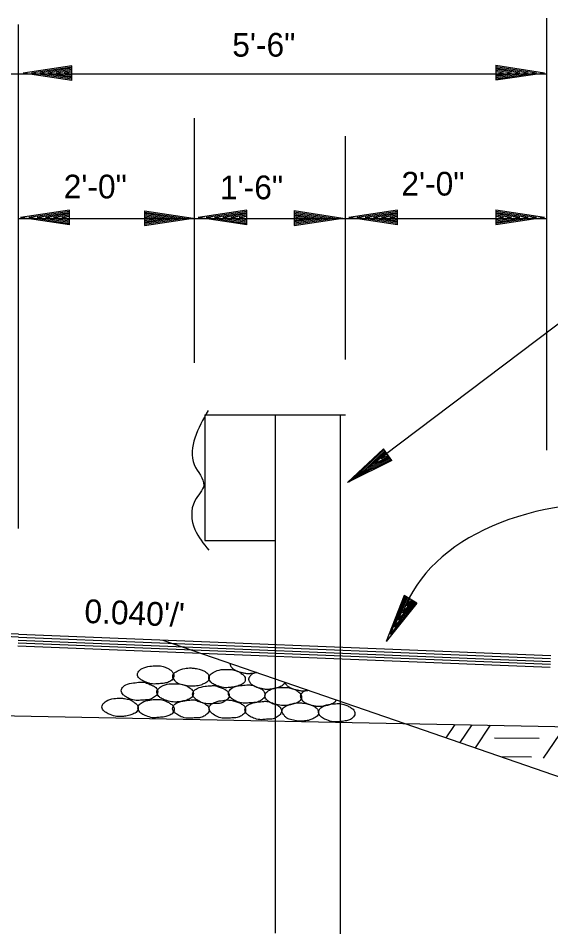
# Model space of a CAD drawing. Extents: x 1926836 to 1933254, y 596317 to 604524.
# Drawn here: x 1928623.7 to 1928757.8, y 602552.3 to 602783 of the extents above; entities that cross this region are included whole.
import ezdxf

# ---------------------------------------------------------------- set-up
doc = ezdxf.new("R2010")
doc.units = 0
doc.layers.add('Default', color=7, linetype='Continuous')
doc.layers.add('R_Annotation', color=7, linetype='Continuous')

msp = doc.modelspace()

# ---------------------------------------------------------------- linework, layer by layer
at = {"layer": 'Default'}
for p, q in [((1928623.71, 602654.37), (1928623.71, 602781.38)), ((1928756.85, 602674.17), (1928756.85, 602782.96)), ((1928637.18, 602771), (1928624.91, 602769.16)), ((1928637.18, 602770.68), (1928626.97, 602769.16)), ((1928637.18, 602770.36), (1928629.07, 602769.16)), ((1928637.18, 602770.06), (1928631.13, 602769.16)), ((1928637.18, 602769.75), (1928633.19, 602769.16)), ((1928637.18, 602769.43), (1928635.25, 602769.16)), ((1928637.18, 602767.3), (1928637.18, 602771)), ((1928743.96, 602771.12), (1928756.24, 602769.26)), ((1928743.96, 602771.12), (1928743.96, 602767.42)), ((1928743.96, 602770.8), (1928754.18, 602769.26)), ((1928743.96, 602770.48), (1928752.07, 602769.26)), ((1928743.96, 602770.19), (1928750.01, 602769.26)), ((1928743.96, 602769.87), (1928747.95, 602769.26)), ((1928743.96, 602769.55), (1928745.9, 602769.26)), ((1928743.96, 602767.42), (1928756.24, 602769.26)), ((1928743.96, 602768.67), (1928747.95, 602769.26)), ((1928743.96, 602768.05), (1928752.07, 602769.26)), ((1928743.96, 602767.74), (1928754.18, 602769.26)), ((1928743.96, 602768.35), (1928750.01, 602769.26)), ((1928743.96, 602768.99), (1928745.9, 602769.26)), ((1928427.69, 602768.94), (1928756.85, 602768.94)), ((1928637.18, 602767.3), (1928624.91, 602769.16)), ((1928637.18, 602767.61), (1928626.97, 602769.16)), ((1928637.18, 602767.93), (1928629.07, 602769.16)), ((1928637.18, 602768.23), (1928631.13, 602769.16)), ((1928637.18, 602768.54), (1928633.19, 602769.16)), ((1928637.18, 602768.86), (1928635.25, 602769.16)), ((1928668.08, 602696.18), (1928668.08, 602757.79)), ((1928706.13, 602696.98), (1928706.13, 602753.3)), ((1928743.96, 602734.68), (1928756.24, 602732.82)), ((1928743.96, 602734.68), (1928743.96, 602730.98)), ((1928623.71, 602732.53), (1928756.85, 602732.53)), ((1928636.52, 602734.59), (1928624.25, 602732.75)), ((1928636.52, 602730.89), (1928624.25, 602732.75)), ((1928636.52, 602734.27), (1928626.3, 602732.75)), ((1928636.52, 602731.2), (1928626.3, 602732.75)), ((1928636.52, 602733.95), (1928628.41, 602732.75)), ((1928636.52, 602731.52), (1928628.41, 602732.75)), ((1928636.52, 602733.65), (1928630.47, 602732.75)), ((1928636.52, 602731.82), (1928630.47, 602732.75)), ((1928636.52, 602733.34), (1928632.53, 602732.75)), ((1928636.52, 602732.14), (1928632.53, 602732.75)), ((1928636.52, 602733.02), (1928634.59, 602732.75)), ((1928636.52, 602732.45), (1928634.59, 602732.75)), ((1928636.52, 602730.89), (1928636.52, 602734.59)), ((1928655.46, 602734.46), (1928667.74, 602732.6)), ((1928655.46, 602734.46), (1928655.46, 602730.76)), ((1928655.46, 602734.14), (1928665.68, 602732.6)), ((1928655.46, 602733.83), (1928663.57, 602732.6)), ((1928655.46, 602733.53), (1928661.51, 602732.6)), ((1928655.46, 602733.21), (1928659.45, 602732.6)), ((1928655.46, 602732.89), (1928657.4, 602732.6)), ((1928655.46, 602730.76), (1928667.74, 602732.6)), ((1928655.46, 602732.01), (1928659.45, 602732.6)), ((1928655.46, 602731.4), (1928663.57, 602732.6)), ((1928655.46, 602731.08), (1928665.68, 602732.6)), ((1928655.46, 602731.69), (1928661.51, 602732.6)), ((1928655.46, 602732.33), (1928657.4, 602732.6)), ((1928681.24, 602734.59), (1928668.96, 602732.75)), ((1928681.24, 602730.89), (1928668.96, 602732.75)), ((1928681.24, 602734.27), (1928671.02, 602732.75)), ((1928681.24, 602731.2), (1928671.02, 602732.75)), ((1928681.24, 602733.95), (1928673.13, 602732.75)), ((1928681.24, 602731.52), (1928673.13, 602732.75)), ((1928681.24, 602733.65), (1928675.19, 602732.75)), ((1928681.24, 602731.82), (1928675.19, 602732.75)), ((1928681.24, 602733.34), (1928677.24, 602732.75)), ((1928681.24, 602732.14), (1928677.24, 602732.75)), ((1928681.24, 602733.02), (1928679.3, 602732.75)), ((1928681.24, 602732.45), (1928679.3, 602732.75)), ((1928681.24, 602730.89), (1928681.24, 602734.59)), ((1928693.17, 602734.49), (1928705.44, 602732.63)), ((1928693.17, 602734.49), (1928693.17, 602730.79)), ((1928693.17, 602734.17), (1928703.39, 602732.63)), ((1928693.17, 602733.85), (1928701.28, 602732.63)), ((1928693.17, 602733.56), (1928699.22, 602732.63)), ((1928693.17, 602733.24), (1928697.16, 602732.63)), ((1928693.17, 602732.92), (1928695.1, 602732.63)), ((1928693.17, 602730.79), (1928705.44, 602732.63)), ((1928693.17, 602732.04), (1928697.16, 602732.63)), ((1928693.17, 602731.42), (1928701.28, 602732.63)), ((1928693.17, 602731.11), (1928703.39, 602732.63)), ((1928693.17, 602731.72), (1928699.22, 602732.63)), ((1928693.17, 602732.36), (1928695.1, 602732.63)), ((1928719.17, 602734.61), (1928706.89, 602732.77)), ((1928719.17, 602730.91), (1928706.89, 602732.77)), ((1928719.17, 602734.29), (1928708.95, 602732.77)), ((1928719.17, 602731.23), (1928708.95, 602732.77)), ((1928719.17, 602733.97), (1928711.06, 602732.77)), ((1928719.17, 602731.55), (1928711.06, 602732.77)), ((1928719.17, 602733.68), (1928713.11, 602732.77)), ((1928719.17, 602731.84), (1928713.11, 602732.77)), ((1928719.17, 602733.36), (1928715.17, 602732.77)), ((1928719.17, 602732.16), (1928715.17, 602732.77)), ((1928719.17, 602733.04), (1928717.23, 602732.77)), ((1928719.17, 602732.48), (1928717.23, 602732.77)), ((1928719.17, 602730.91), (1928719.17, 602734.61)), ((1928743.96, 602734.37), (1928754.18, 602732.82)), ((1928743.96, 602734.05), (1928752.07, 602732.82)), ((1928743.96, 602733.75), (1928750.01, 602732.82)), ((1928743.96, 602733.43), (1928747.95, 602732.82)), ((1928743.96, 602733.12), (1928745.9, 602732.82)), ((1928743.96, 602730.98), (1928756.24, 602732.82)), ((1928743.96, 602732.23), (1928747.95, 602732.82)), ((1928743.96, 602731.62), (1928752.07, 602732.82)), ((1928743.96, 602731.3), (1928754.18, 602732.82)), ((1928743.96, 602731.91), (1928750.01, 602732.82)), ((1928743.96, 602732.55), (1928745.9, 602732.82)), ((1928706.94, 602666.13), (1928775.96, 602718.29)), ((1928670.63, 602683.06), (1928670.63, 602651.35)), ((1928670.63, 602683.06), (1928706.13, 602683.06)), ((1928688.39, 602683.06), (1928688.39, 602552.42)), ((1928704.71, 602682.91), (1928704.71, 602552.29)), ((1928715.65, 602674.51), (1928706.62, 602665.99)), ((1928715.84, 602674.27), (1928708.29, 602667.14)), ((1928716.04, 602673.98), (1928710.08, 602668.41)), ((1928716.16, 602673.72), (1928711.74, 602669.56)), ((1928716.35, 602673.51), (1928713.41, 602670.73)), ((1928716.99, 602672.55), (1928713.41, 602670.73)), ((1928716.52, 602673.24), (1928715.11, 602671.92)), ((1928716.87, 602672.83), (1928715.11, 602671.92)), ((1928717.73, 602671.52), (1928715.65, 602674.51)), ((1928717.73, 602671.52), (1928706.62, 602665.99)), ((1928717.58, 602671.75), (1928708.29, 602667.14)), ((1928717.36, 602672.02), (1928710.08, 602668.41)), ((1928717.19, 602672.28), (1928711.74, 602669.56)), ((1928670.63, 602651.35), (1928688.39, 602651.35)), ((1928720.86, 602637.49), (1928716.3, 602625.92)), ((1928724.04, 602635.62), (1928716.3, 602625.92)), ((1928721.1, 602637.29), (1928717.33, 602627.71)), ((1928723.8, 602635.79), (1928717.33, 602627.71)), ((1928721.4, 602637.14), (1928718.38, 602629.55)), ((1928723.48, 602635.92), (1928718.38, 602629.55)), ((1928721.64, 602637), (1928719.39, 602631.29)), ((1928723.23, 602636.09), (1928719.39, 602631.29)), ((1928721.93, 602636.85), (1928720.44, 602633.1)), ((1928722.96, 602636.24), (1928720.44, 602633.1)), ((1928724.04, 602635.62), (1928720.86, 602637.49)), ((1928722.23, 602636.68), (1928721.49, 602634.86)), ((1928722.69, 602636.41), (1928721.49, 602634.86)), ((1928623.71, 602627.76), (1928476.7, 602633.64)), ((1928623.71, 602627.02), (1928476.7, 602632.9)), ((1928623.64, 602626.29), (1928757.74, 602620.92)), ((1928623.67, 602627.02), (1928757.76, 602621.66)), ((1928623.71, 602627.76), (1928757.8, 602622.39)), ((1928660.08, 602626.3), (1928721.07, 602605.25)), ((1928623.58, 602624.82), (1928757.68, 602619.45)), ((1928623.61, 602625.55), (1928757.71, 602620.19)), ((1928423.27, 602611.17), (1928815.02, 602603.38)), ((1928721.07, 602605.25), (1928844.61, 602562.6))]:
    msp.add_line(p, q, dxfattribs=at)
msp.add_ellipse((1928779.93, 602620.52), major_axis=(-60.55, 7.39), ratio=0.655798, start_param=4.712389, end_param=6.093533, dxfattribs=at)
for points in [[(1928671.49, 602684.09), (1928668.15, 602677.2), (1928667.98, 602670.49), (1928670.38, 602665.32), (1928668.15, 602661.4), (1928668.15, 602654.17), (1928671.68, 602648.95)], [(1928658.43, 602619.78), (1928656.81, 602619.68), (1928654.85, 602619.09), (1928653.82, 602618.16), (1928653.67, 602617.62), (1928654.16, 602616.64), (1928654.75, 602616.2), (1928655.88, 602615.66), (1928657.45, 602615.22), (1928658.28, 602615.22), (1928659.45, 602615.32), (1928660.78, 602615.47), (1928661.81, 602615.86), (1928662.69, 602616.69), (1928662.84, 602617.33), (1928662.54, 602618.21), (1928661.91, 602618.8), (1928661.22, 602619.19), (1928660.14, 602619.63), (1928659.45, 602619.78), (1928658.43, 602619.78)], [(1928676.96, 602620.48), (1928676.96, 602620.44), (1928676.96, 602620.38), (1928676.97, 602620.31), (1928677.04, 602620.04), (1928677.16, 602619.78), (1928677.31, 602619.52), (1928677.4, 602619.4), (1928677.51, 602619.28), (1928677.76, 602619.03), (1928678.04, 602618.84), (1928678.31, 602618.7), (1928678.57, 602618.57), (1928678.84, 602618.45), (1928679.12, 602618.35), (1928679.9, 602618.13), (1928680.69, 602617.96), (1928681.11, 602617.89), (1928681.31, 602617.87), (1928681.52, 602617.86), (1928682.11, 602617.89), (1928682.41, 602617.92), (1928682.7, 602617.96), (1928683.22, 602618.04), (1928683.73, 602618.14)], [(1928667.21, 602619.26), (1928665.59, 602619.16), (1928663.68, 602618.47), (1928662.7, 602617.69), (1928662.55, 602617.15), (1928663.09, 602616.12), (1928663.53, 602615.58), (1928664.71, 602615.09), (1928666.18, 602614.75), (1928667.01, 602614.65), (1928668.23, 602614.7), (1928669.61, 602614.94), (1928670.59, 602615.38), (1928671.62, 602616.17), (1928671.76, 602616.81), (1928671.47, 602617.69), (1928670.73, 602618.33), (1928670, 602618.67), (1928668.92, 602619.01), (1928668.23, 602619.16), (1928667.21, 602619.26)], [(1928676.34, 602618.89), (1928674.73, 602618.84), (1928672.77, 602618.15), (1928671.79, 602617.27), (1928671.64, 602616.68), (1928672.18, 602615.7), (1928672.72, 602615.26), (1928673.8, 602614.77), (1928675.36, 602614.33), (1928676.2, 602614.28), (1928677.37, 602614.38), (1928678.7, 602614.63), (1928679.73, 602615.02), (1928680.71, 602615.8), (1928680.85, 602616.39), (1928680.56, 602617.27), (1928679.82, 602617.86), (1928679.14, 602618.35), (1928678.06, 602618.69), (1928677.37, 602618.84), (1928676.34, 602618.89)], [(1928683.59, 602618.19), (1928683.29, 602618.07), (1928683.05, 602617.96), (1928682.82, 602617.83), (1928682.52, 602617.65), (1928682.27, 602617.44), (1928682.05, 602617.19), (1928681.94, 602617.05), (1928681.84, 602616.9), (1928681.76, 602616.77), (1928681.71, 602616.63), (1928681.68, 602616.5), (1928681.68, 602616.43), (1928681.69, 602616.36), (1928681.76, 602616.1), (1928681.88, 602615.83), (1928682.03, 602615.58), (1928682.13, 602615.46), (1928682.23, 602615.34), (1928682.48, 602615.09), (1928682.77, 602614.89), (1928683.03, 602614.75), (1928683.29, 602614.62), (1928683.57, 602614.5), (1928683.84, 602614.4), (1928684.62, 602614.18), (1928685.41, 602614.01), (1928686.25, 602613.91), (1928686.39, 602613.92), (1928686.54, 602613.92), (1928686.83, 602613.94), (1928687.42, 602614.01), (1928687.76, 602614.06), (1928688.09, 602614.12), (1928688.42, 602614.18), (1928688.74, 602614.26), (1928689.01, 602614.33), (1928689.27, 602614.42), (1928689.52, 602614.53), (1928689.77, 602614.65), (1928690.05, 602614.79), (1928690.31, 602614.96), (1928690.54, 602615.17), (1928690.65, 602615.29), (1928690.75, 602615.43), (1928690.82, 602615.55), (1928690.87, 602615.67)], [(1928654.37, 602615.69), (1928652.65, 602615.49), (1928650.74, 602615), (1928649.76, 602614.07), (1928649.61, 602613.53), (1928650.1, 602612.5), (1928650.69, 602612.06), (1928651.77, 602611.47), (1928653.34, 602611.08), (1928654.12, 602611.08), (1928655.35, 602611.18), (1928656.72, 602611.28), (1928657.75, 602611.77), (1928658.63, 602612.6), (1928658.78, 602613.24), (1928658.48, 602614.12), (1928657.75, 602614.71), (1928657.06, 602615), (1928655.98, 602615.44), (1928655.35, 602615.64), (1928654.37, 602615.69)], [(1928663.26, 602615.27), (1928661.64, 602615.22), (1928659.68, 602614.58), (1928658.7, 602613.65), (1928658.56, 602613.11), (1928659.1, 602612.09), (1928659.63, 602611.64), (1928660.71, 602611.15), (1928662.28, 602610.76), (1928663.11, 602610.66), (1928664.29, 602610.76), (1928665.61, 602611.01), (1928666.64, 602611.4), (1928667.62, 602612.18), (1928667.77, 602612.82), (1928667.48, 602613.7), (1928666.74, 602614.29), (1928666.05, 602614.73), (1928664.98, 602615.07), (1928664.29, 602615.22), (1928663.26, 602615.27)], [(1928672.32, 602614.77), (1928670.7, 602614.63), (1928668.74, 602614.09), (1928667.71, 602613.16), (1928667.57, 602612.62), (1928668.1, 602611.64), (1928668.64, 602611.2), (1928669.77, 602610.56), (1928671.29, 602610.22), (1928672.12, 602610.22), (1928673.3, 602610.31), (1928674.72, 602610.36), (1928675.7, 602610.85), (1928676.63, 602611.69), (1928676.78, 602612.32), (1928676.48, 602613.2), (1928675.8, 602613.79), (1928675.06, 602614.14), (1928674.03, 602614.48), (1928673.35, 602614.77), (1928672.32, 602614.77)], [(1928681.24, 602615), (1928679.62, 602614.81), (1928677.71, 602614.32), (1928676.73, 602613.38), (1928676.58, 602612.84), (1928677.12, 602611.82), (1928677.66, 602611.37), (1928678.74, 602610.79), (1928680.31, 602610.39), (1928681.09, 602610.39), (1928682.32, 602610.49), (1928683.64, 602610.59), (1928684.72, 602611.08), (1928685.65, 602611.91), (1928685.79, 602612.55), (1928685.5, 602613.43), (1928684.77, 602614.02), (1928684.03, 602614.32), (1928683, 602614.81), (1928682.27, 602614.95), (1928681.24, 602615)], [(1928690.82, 602615.69), (1928690.9, 602615.49), (1928691.01, 602615.29), (1928691.14, 602615.1), (1928691.29, 602614.91), (1928691.55, 602614.66), (1928691.83, 602614.47), (1928692.09, 602614.33), (1928692.36, 602614.2), (1928692.63, 602614.08), (1928692.91, 602613.98), (1928693.69, 602613.76), (1928694.48, 602613.59), (1928694.89, 602613.52), (1928695.1, 602613.5), (1928695.31, 602613.49), (1928695.9, 602613.52), (1928696.49, 602613.59), (1928696.79, 602613.63)], [(1928690.5, 602614.36), (1928688.88, 602614.32), (1928686.92, 602613.68), (1928685.94, 602612.75), (1928685.79, 602612.21), (1928686.33, 602611.18), (1928686.87, 602610.74), (1928687.95, 602610.25), (1928689.52, 602609.86), (1928690.35, 602609.76), (1928691.53, 602609.86), (1928692.85, 602610.1), (1928693.88, 602610.49), (1928694.86, 602611.28), (1928695.01, 602611.91), (1928694.71, 602612.8), (1928693.98, 602613.38), (1928693.29, 602613.83), (1928692.21, 602614.17), (1928691.53, 602614.32), (1928690.5, 602614.36)], [(1928696.37, 602613.77), (1928696.11, 602613.66), (1928695.98, 602613.59), (1928695.85, 602613.52), (1928695.56, 602613.34), (1928695.3, 602613.13), (1928695.08, 602612.88), (1928694.97, 602612.74), (1928694.87, 602612.59), (1928694.79, 602612.46), (1928694.74, 602612.32), (1928694.71, 602612.18), (1928694.71, 602612.12), (1928694.72, 602612.05), (1928694.79, 602611.78), (1928694.91, 602611.52), (1928695.07, 602611.27), (1928695.16, 602611.14), (1928695.26, 602611.02), (1928695.51, 602610.77), (1928695.8, 602610.58), (1928696.06, 602610.44), (1928696.33, 602610.31), (1928696.6, 602610.19), (1928696.88, 602610.09), (1928697.65, 602609.87), (1928698.44, 602609.7), (1928699.28, 602609.6), (1928699.42, 602609.6), (1928699.57, 602609.61), (1928699.87, 602609.63), (1928700.45, 602609.7), (1928700.79, 602609.75), (1928701.12, 602609.81), (1928701.45, 602609.87), (1928701.78, 602609.94), (1928702.04, 602610.02), (1928702.3, 602610.11), (1928702.55, 602610.22), (1928702.81, 602610.34), (1928703.08, 602610.48), (1928703.34, 602610.65), (1928703.57, 602610.86), (1928703.68, 602610.98), (1928703.73, 602611.05), (1928703.79, 602611.12), (1928703.83, 602611.2)], [(1928649.37, 602611.61), (1928647.75, 602611.56), (1928645.79, 602610.88), (1928644.86, 602609.99), (1928644.71, 602609.41), (1928645.2, 602608.43), (1928645.79, 602607.99), (1928646.82, 602607.5), (1928648.44, 602607.05), (1928649.22, 602607.01), (1928650.45, 602607.1), (1928651.77, 602607.35), (1928652.8, 602607.74), (1928653.73, 602608.52), (1928653.88, 602609.11), (1928653.58, 602609.99), (1928652.85, 602610.58), (1928652.16, 602611.07), (1928651.08, 602611.42), (1928650.4, 602611.56), (1928649.37, 602611.61)], [(1928658.43, 602611.33), (1928656.82, 602611.18), (1928654.86, 602610.59), (1928653.93, 602609.71), (1928653.78, 602609.12), (1928654.27, 602608.14), (1928654.76, 602607.7), (1928655.89, 602607.21), (1928657.41, 602606.72), (1928658.24, 602606.72), (1928659.46, 602606.82), (1928660.84, 602607.01), (1928661.82, 602607.36), (1928662.8, 602608.24), (1928662.94, 602608.83), (1928662.65, 602609.71), (1928661.91, 602610.3), (1928661.18, 602610.74), (1928660.15, 602611.13), (1928659.46, 602611.28), (1928658.43, 602611.33)], [(1928667.25, 602611.2), (1928665.63, 602611), (1928663.67, 602610.46), (1928662.69, 602609.58), (1928662.54, 602608.99), (1928663.08, 602608.01), (1928663.62, 602607.57), (1928664.7, 602606.98), (1928666.22, 602606.59), (1928667.05, 602606.59), (1928668.28, 602606.69), (1928669.6, 602606.78), (1928670.63, 602607.23), (1928671.61, 602608.11), (1928671.75, 602608.7), (1928671.46, 602609.58), (1928670.73, 602610.17), (1928669.99, 602610.51), (1928668.91, 602610.9), (1928668.28, 602611.15), (1928667.25, 602611.2)], [(1928676.47, 602611.2), (1928674.8, 602611.01), (1928672.84, 602610.47), (1928671.86, 602609.59), (1928671.71, 602609), (1928672.25, 602608.02), (1928672.79, 602607.58), (1928673.92, 602606.94), (1928675.44, 602606.6), (1928676.22, 602606.6), (1928677.45, 602606.65), (1928678.82, 602606.79), (1928679.85, 602607.23), (1928680.78, 602608.12), (1928680.93, 602608.7), (1928680.63, 602609.59), (1928679.9, 602610.17), (1928679.16, 602610.52), (1928678.13, 602610.86), (1928677.5, 602611.06), (1928676.47, 602611.2)], [(1928685.5, 602610.84), (1928683.79, 602610.64), (1928681.92, 602610.15), (1928680.89, 602609.22), (1928680.75, 602608.68), (1928681.29, 602607.65), (1928681.82, 602607.21), (1928682.95, 602606.62), (1928684.47, 602606.23), (1928685.26, 602606.23), (1928686.48, 602606.33), (1928687.9, 602606.43), (1928688.88, 602606.92), (1928689.81, 602607.75), (1928689.96, 602608.39), (1928689.67, 602609.27), (1928688.93, 602609.86), (1928688.24, 602610.15), (1928687.17, 602610.54), (1928686.53, 602610.79), (1928685.5, 602610.84)], [(1928694.74, 602610.46), (1928693.12, 602610.36), (1928691.21, 602609.68), (1928690.23, 602608.89), (1928690.08, 602608.35), (1928690.62, 602607.32), (1928691.06, 602606.78), (1928692.24, 602606.29), (1928693.71, 602605.95), (1928694.54, 602605.85), (1928695.77, 602605.9), (1928697.14, 602606.15), (1928698.12, 602606.59), (1928699.15, 602607.37), (1928699.29, 602608.01), (1928699, 602608.89), (1928698.27, 602609.53), (1928697.53, 602609.87), (1928696.45, 602610.22), (1928695.77, 602610.36), (1928694.74, 602610.46)], [(1928703.95, 602610.27), (1928702.33, 602610.13), (1928700.37, 602609.54), (1928699.44, 602608.66), (1928699.29, 602608.07), (1928699.78, 602607.09), (1928700.27, 602606.65), (1928701.4, 602606.16), (1928702.92, 602605.67), (1928703.75, 602605.67), (1928704.98, 602605.76), (1928706.35, 602605.96), (1928707.33, 602606.3), (1928708.31, 602607.19), (1928708.46, 602607.77), (1928708.16, 602608.66), (1928707.43, 602609.24), (1928706.69, 602609.68), (1928705.67, 602610.08), (1928704.98, 602610.22), (1928703.95, 602610.27)]]:
    msp.add_spline(points, degree=3, dxfattribs=at)
at = {"layer": 'R_Annotation'}
for p, q in [((1928731.49, 602601.65), (1928733.74, 602605)), ((1928734.96, 602600.45), (1928737.97, 602604.91)), ((1928738.81, 602599.12), (1928742.65, 602604.82)), ((1928755.96, 602596.5), (1928761.32, 602604.45)), ((1928743.59, 602601.67), (1928754.85, 602601.58)), ((1928745.17, 602596.93), (1928752.91, 602596.87))]:
    msp.add_line(p, q, dxfattribs=at)

# ---------------------------------------------------------------- texts
at = {"layer": 'Default'}
for s, rotation, p in [('5\'-6"', 360, (1928677.56, 602773.3)), ('2\'-0"', 360, (1928720.17, 602738.29)), ('2\'-0"', 360, (1928635.1, 602737.58)), ('1\'-6"', 360, (1928674.47, 602737.36)), ("0.040'/'", 357.7094, (1928640.22, 602630.61))]:
    msp.add_text(s, height=5.975, rotation=rotation, dxfattribs=at).set_placement(p)

doc.saveas('drawing.dxf')
